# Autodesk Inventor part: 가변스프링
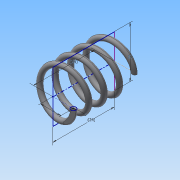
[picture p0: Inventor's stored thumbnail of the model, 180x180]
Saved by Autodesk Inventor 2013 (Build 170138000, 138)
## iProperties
Created: 2015-09
Part Number: 가변스프링
Material: 일반
Document SubType Name: Modeling
Designer: Administrator
Density: 1 g/cm^3
Author: Administrator
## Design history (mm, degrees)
sketch "스케치1"
  geometry: L1 (0, 0)-(0, 42); L2 (0, 0)-(8, 0); L3 (0, 42)-(8, 42); C1 r 1 at (8, 0)
  constraints: 6 end point, 2 parallel, 1 centre point, 1 coincident, 1 perpendicular, 1 vertical
  dimensions: "d0" = 42 distance of L1.start L1.end (derived); "d2" = 2 diameter of C1; "d3" = 8 distance of L1.start L2.end
feature "코일1" pitch "d4" = 10; turns "d6" = 4; dims "d5" = 42 (= d0), "d7" = 0, angle "d8" = 90 deg, angle "d9" = 90 deg, "d10" = 0, "d11" = 0
sketch "스케치2"
  geometry: L1 (42, 10)-(0, 10); L2 (0, 10)-(0, -10); L3 (0, -10)-(42, -10); L4 (42, -10)-(42, 10); 2 further points
  constraints: 8 end point, 2 parallel, 1 coincident, 1 horizontal, 1 midpoint, 1 perpendicular
  dimensions: "d12" = 42 distance of L2.end L3.end (derived); "d14" = 20 distance of L3.end L1.start
extrude "돌출1" sketch "스케치2" stored distance "d15" = 10; taper "d16" = 0 deg
node "솔리드1"
